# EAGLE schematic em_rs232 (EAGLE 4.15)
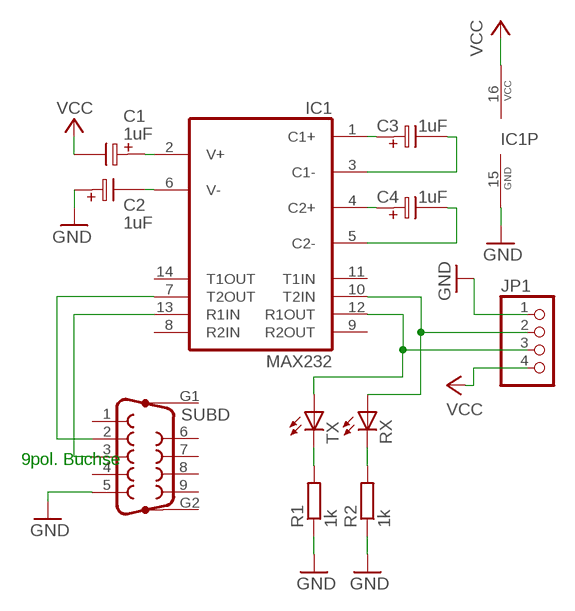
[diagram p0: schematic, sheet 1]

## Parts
C1  1uF  ELC-2,5  [ES-2,5]
C2  1uF  ELC-2,5  [ES-2,5]
C3  1uF  ELC-2,5  [ES-2,5]
C4  1uF  ELC-2,5  [ES-2,5]
IC1  MAX232  [16PIN]
JP1  PINHD-1X4  [1X04]
R1  1k  R-EU_0204/5  [0204/5]
R2  1k  R-EU_0204/5  [0204/5]
RX  LED3MM  [LED3MM]
SUBD  F09HP  [F09HP]
TX  LED3MM  [LED3MM]

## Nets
C1+: C3.1 IC1.1(C1+)
C1-: C3.2 IC1.3(C1-)
C2+: C4.1 IC1.4(C2+)
C2-: C4.2 IC1.5(C2-)
GND: C2.1 IC1.15(GND) JP1.1 R1.1 R2.1 SUBD.5
N$1: IC1.7(T2OUT) SUBD.2
N$2: IC1.12(R1OUT) JP1.3 TX.A
N$3: IC1.10(T2IN) JP1.2 RX.A
N$4: R1.2 TX.K(C)
N$5: R2.2 RX.K(C)
R1IN: IC1.13(R1IN) SUBD.3
V+: C1.1 IC1.2(V+)
V-: C2.2 IC1.6(V-)
VCC: C1.2 IC1.16(VCC) JP1.4
Unconnected: IC1.8(R2IN) IC1.9(R2OUT) IC1.11(T1IN) IC1.14(T1OUT) SUBD.1 SUBD.4 SUBD.6 SUBD.7 SUBD.8 SUBD.9 SUBD.G1 SUBD.G2

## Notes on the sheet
- 9pol. Buchse

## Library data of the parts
C1-C4 = DISCRETE:ELC-2,5
IC1 = MAXIM:MAX232
JP1 = pinhead:PINHD-1X4: PIN HEADER
R1 R2 = rcl:R-EU_: RESISTOR, European symbol
RX TX = led:LED: LED
SUBD = SUBD-A:F09HP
